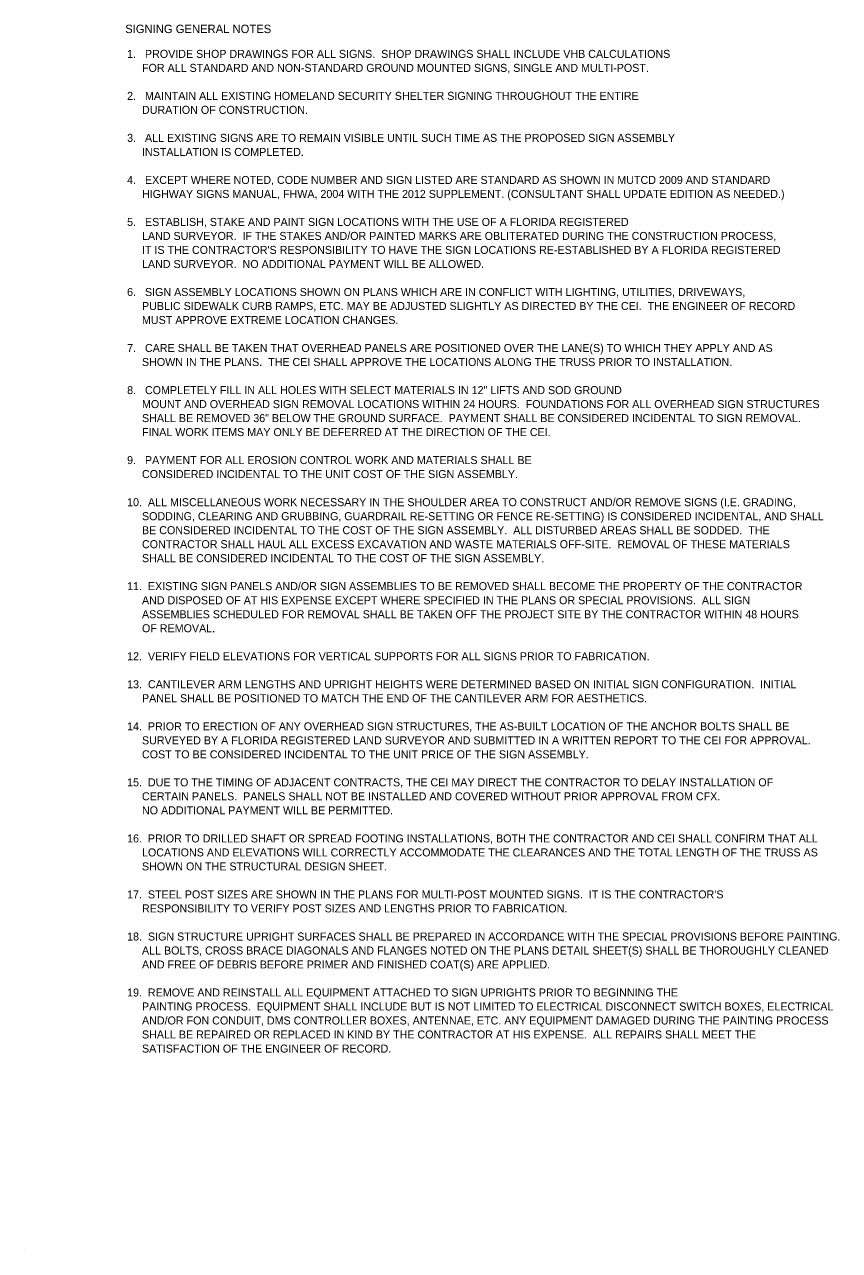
# Model space of a CAD drawing. Extents: x 2479946 to 2481498, y 3680184 to 3681234.
# Drawn here: x 2479946 to 2480633, y 3680184 to 3681218 of the extents above; entities that cross this region are included whole.
import ezdxf

# ---------------------------------------------------------------- set-up
doc = ezdxf.new("R2010")
doc.units = 0
doc.layers.add('AdhocPoint_dp', color=7, linetype='Continuous')
doc.layers.add('TextLabel', color=7, linetype='Continuous')

msp = doc.modelspace()

# ---------------------------------------------------------------- linework, layer by layer
at = {"layer": 'AdhocPoint_dp'}
msp.add_line((2479945.9, 3680184.2), (2479945.9, 3680184.2), dxfattribs=at)

# ---------------------------------------------------------------- texts
at = {"layer": 'TextLabel'}
for s, height, p in [('SIGNING GENERAL NOTES', 7.08, (2480030.8, 3681210.7)), ('1.   PROVIDE SHOP DRAWINGS FOR ALL SIGNS.  SHOP DRAWINGS SHALL INCLUDE VHB CALCULATIONS ', 6.75, (2480032.4, 3681189.8)), ('     FOR ALL STANDARD AND NON-STANDARD GROUND MOUNTED SIGNS, SINGLE AND MULTI-POST.', 6.75, (2480032.4, 3681178)), ('2.   MAINTAIN ALL EXISTING HOMELAND SECURITY SHELTER SIGNING THROUGHOUT THE ENTIRE ', 6.75, (2480032.4, 3681154.4)), ('     DURATION OF CONSTRUCTION.', 6.75, (2480032.4, 3681142.6)), ('3.   ALL EXISTING SIGNS ARE TO REMAIN VISIBLE UNTIL SUCH TIME AS THE PROPOSED SIGN ASSEMBLY ', 6.75, (2480032.4, 3681119)), ('     INSTALLATION IS COMPLETED.', 6.75, (2480032.4, 3681107.1)), ('4.   EXCEPT WHERE NOTED, CODE NUMBER AND SIGN LISTED ARE STANDARD AS SHOWN IN MUTCD 2009 AND STANDARD ', 6.75, (2480032.4, 3681083.5)), ('     HIGHWAY SIGNS MANUAL, FHWA, 2004 WITH THE 2012 SUPPLEMENT. (CONSULTANT SHALL UPDATE EDITION AS NEEDED.)', 6.75, (2480032.4, 3681071.7)), ('5.   ESTABLISH, STAKE AND PAINT SIGN LOCATIONS WITH THE USE OF A FLORIDA REGISTERED ', 6.75, (2480032.4, 3681048.1)), ('     LAND SURVEYOR.  IF THE STAKES AND/OR PAINTED MARKS ARE OBLITERATED DURING THE CONSTRUCTION PROCESS, ', 6.75, (2480032.4, 3681036.3)), ("     IT IS THE CONTRACTOR'S RESPONSIBILITY TO HAVE THE SIGN LOCATIONS RE-ESTABLISHED BY A FLORIDA REGISTERED ", 6.75, (2480032.4, 3681024.5)), ('     LAND SURVEYOR.  NO ADDITIONAL PAYMENT WILL BE ALLOWED.', 6.75, (2480032.4, 3681012.6)), ('6.   SIGN ASSEMBLY LOCATIONS SHOWN ON PLANS WHICH ARE IN CONFLICT WITH LIGHTING, UTILITIES, DRIVEWAYS, ', 6.75, (2480032.4, 3680989)), ('     PUBLIC SIDEWALK CURB RAMPS, ETC. MAY BE ADJUSTED SLIGHTLY AS DIRECTED BY THE CEI.  THE ENGINEER OF RECORD', 6.75, (2480032.4, 3680977.2)), ('     MUST APPROVE EXTREME LOCATION CHANGES. ', 6.75, (2480032.4, 3680965.4)), ('7.   CARE SHALL BE TAKEN THAT OVERHEAD PANELS ARE POSITIONED OVER THE LANE(S) TO WHICH THEY APPLY AND AS ', 6.75, (2480032.4, 3680941.8)), ('     SHOWN IN THE PLANS.  THE CEI SHALL APPROVE THE LOCATIONS ALONG THE TRUSS PRIOR TO INSTALLATION.', 6.75, (2480032.4, 3680930)), ('8.   COMPLETELY FILL IN ALL HOLES WITH SELECT MATERIALS IN 12" LIFTS AND SOD GROUND ', 6.75, (2480032.4, 3680906.3)), ('     MOUNT AND OVERHEAD SIGN REMOVAL LOCATIONS WITHIN 24 HOURS.  FOUNDATIONS FOR ALL OVERHEAD SIGN STRUCTURES ', 6.75, (2480032.4, 3680894.5)), ('     SHALL BE REMOVED 36" BELOW THE GROUND SURFACE.  PAYMENT SHALL BE CONSIDERED INCIDENTAL TO SIGN REMOVAL.', 6.75, (2480032.4, 3680882.7)), ('     FINAL WORK ITEMS MAY ONLY BE DEFERRED AT THE DIRECTION OF THE CEI.', 6.75, (2480032.4, 3680870.9)), ('9.   PAYMENT FOR ALL EROSION CONTROL WORK AND MATERIALS SHALL BE', 6.75, (2480032.4, 3680847.3)), ('     CONSIDERED INCIDENTAL TO THE UNIT COST OF THE SIGN ASSEMBLY.', 6.75, (2480032.4, 3680835.5)), ('10.  ALL MISCELLANEOUS WORK NECESSARY IN THE SHOULDER AREA TO CONSTRUCT AND/OR REMOVE SIGNS (I.E. GRADING, ', 6.75, (2480032.4, 3680811.8)), ('     SODDING, CLEARING AND GRUBBING, GUARDRAIL RE-SETTING OR FENCE RE-SETTING) IS CONSIDERED INCIDENTAL, AND SHALL ', 6.75, (2480032.4, 3680800)), ('     BE CONSIDERED INCIDENTAL TO THE COST OF THE SIGN ASSEMBLY.  ALL DISTURBED AREAS SHALL BE SODDED.  THE  ', 6.75, (2480032.4, 3680788.2)), ('     CONTRACTOR SHALL HAUL ALL EXCESS EXCAVATION AND WASTE MATERIALS OFF-SITE.  REMOVAL OF THESE MATERIALS  ', 6.75, (2480032.4, 3680776.4)), ('     SHALL BE CONSIDERED INCIDENTAL TO THE COST OF THE SIGN ASSEMBLY.', 6.75, (2480032.4, 3680764.6)), ('11.  EXISTING SIGN PANELS AND/OR SIGN ASSEMBLIES TO BE REMOVED SHALL BECOME THE PROPERTY OF THE CONTRACTOR ', 6.75, (2480032.4, 3680741)), ('     AND DISPOSED OF AT HIS EXPENSE EXCEPT WHERE SPECIFIED IN THE PLANS OR SPECIAL PROVISIONS.  ALL SIGN ', 6.75, (2480032.4, 3680729.1)), ('     ASSEMBLIES SCHEDULED FOR REMOVAL SHALL BE TAKEN OFF THE PROJECT SITE BY THE CONTRACTOR WITHIN 48 HOURS ', 6.75, (2480032.4, 3680717.3)), ('     OF REMOVAL.', 6.75, (2480032.4, 3680705.5)), ('12.  VERIFY FIELD ELEVATIONS FOR VERTICAL SUPPORTS FOR ALL SIGNS PRIOR TO FABRICATION.', 6.75, (2480032.4, 3680681.9)), ('13.  CANTILEVER ARM LENGTHS AND UPRIGHT HEIGHTS WERE DETERMINED BASED ON INITIAL SIGN CONFIGURATION.  INITIAL', 6.75, (2480032.4, 3680658.3)), ('     PANEL SHALL BE POSITIONED TO MATCH THE END OF THE CANTILEVER ARM FOR AESTHETICS.', 6.75, (2480032.4, 3680646.5)), ('14.  PRIOR TO ERECTION OF ANY OVERHEAD SIGN STRUCTURES, THE AS-BUILT LOCATION OF THE ANCHOR BOLTS SHALL BE ', 6.75, (2480032.4, 3680622.8)), ('     SURVEYED BY A FLORIDA REGISTERED LAND SURVEYOR AND SUBMITTED IN A WRITTEN REPORT TO THE CEI FOR APPROVAL.  ', 6.75, (2480032.4, 3680611)), ('     COST TO BE CONSIDERED INCIDENTAL TO THE UNIT PRICE OF THE SIGN ASSEMBLY.', 6.75, (2480032.4, 3680599.2)), ('15.  DUE TO THE TIMING OF ADJACENT CONTRACTS, THE CEI MAY DIRECT THE CONTRACTOR TO DELAY INSTALLATION OF', 6.75, (2480032.4, 3680575.6)), ('     CERTAIN PANELS.  PANELS SHALL NOT BE INSTALLED AND COVERED WITHOUT PRIOR APPROVAL FROM CFX.', 6.75, (2480032.4, 3680563.8)), ('     NO ADDITIONAL PAYMENT WILL BE PERMITTED.', 6.75, (2480032.4, 3680552)), ('16.  PRIOR TO DRILLED SHAFT OR SPREAD FOOTING INSTALLATIONS, BOTH THE CONTRACTOR AND CEI SHALL CONFIRM THAT ALL', 6.75, (2480032.4, 3680528.3)), ('     LOCATIONS AND ELEVATIONS WILL CORRECTLY ACCOMMODATE THE CLEARANCES AND THE TOTAL LENGTH OF THE TRUSS AS', 6.75, (2480032.4, 3680516.5)), ('     SHOWN ON THE STRUCTURAL DESIGN SHEET.', 6.75, (2480032.4, 3680504.7)), ("17.  STEEL POST SIZES ARE SHOWN IN THE PLANS FOR MULTI-POST MOUNTED SIGNS.  IT IS THE CONTRACTOR'S ", 6.75, (2480032.4, 3680481.1)), ('     RESPONSIBILITY TO VERIFY POST SIZES AND LENGTHS PRIOR TO FABRICATION.', 6.75, (2480032.4, 3680469.3)), ('18.  SIGN STRUCTURE UPRIGHT SURFACES SHALL BE PREPARED IN ACCORDANCE WITH THE SPECIAL PROVISIONS BEFORE PAINTING.', 6.75, (2480032.4, 3680445.6)), ('     ALL BOLTS, CROSS BRACE DIAGONALS AND FLANGES NOTED ON THE PLANS DETAIL SHEET(S) SHALL BE THOROUGHLY CLEANED', 6.75, (2480032.4, 3680433.8)), ('     AND FREE OF DEBRIS BEFORE PRIMER AND FINISHED COAT(S) ARE APPLIED.', 6.75, (2480032.4, 3680422)), ('19.  REMOVE AND REINSTALL ALL EQUIPMENT ATTACHED TO SIGN UPRIGHTS PRIOR TO BEGINNING THE', 6.75, (2480032.4, 3680398.4)), ('     PAINTING PROCESS.  EQUIPMENT SHALL INCLUDE BUT IS NOT LIMITED TO ELECTRICAL DISCONNECT SWITCH BOXES, ELECTRICAL', 6.75, (2480032.4, 3680386.6)), ('     AND/OR FON CONDUIT, DMS CONTROLLER BOXES, ANTENNAE, ETC. ANY EQUIPMENT DAMAGED DURING THE PAINTING PROCESS ', 6.75, (2480032.4, 3680374.8)), ('     SHALL BE REPAIRED OR REPLACED IN KIND BY THE CONTRACTOR AT HIS EXPENSE.  ALL REPAIRS SHALL MEET THE ', 6.75, (2480032.4, 3680363)), ('     SATISFACTION OF THE ENGINEER OF RECORD.', 6.75, (2480032.4, 3680351.1))]:
    msp.add_text(s, height=height, dxfattribs=at).set_placement(p)

doc.saveas('drawing.dxf')
